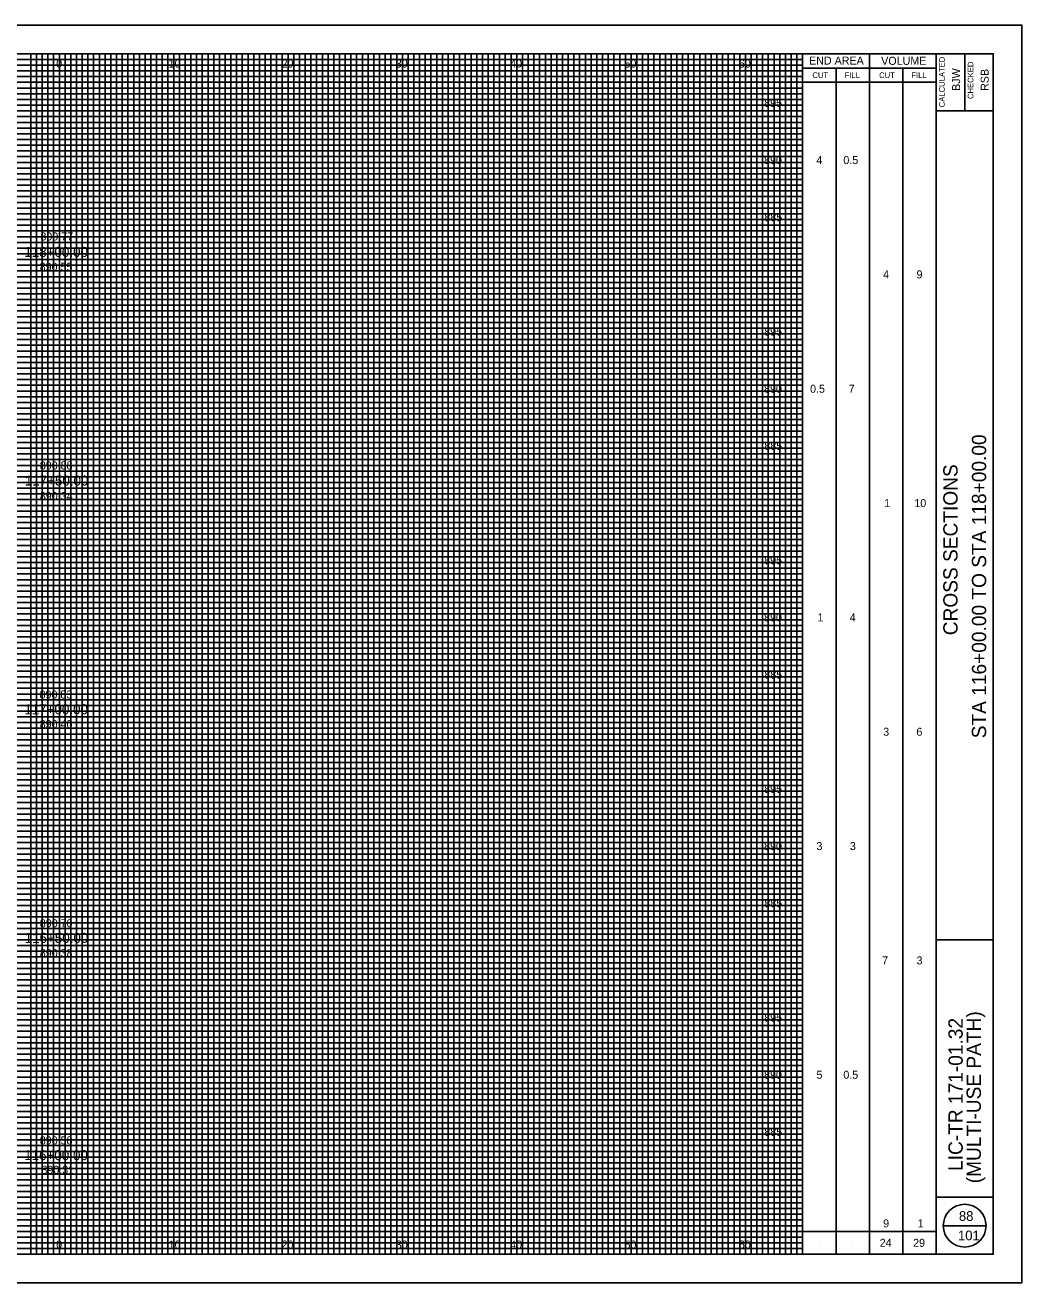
# Model space of a CAD drawing. Extents: x -10 to 160, y -2 to 3672.
# Drawn here: x 72.8 to 160, y 2182.5 to 2292.5 of the extents above; entities that cross this region are included whole.
import ezdxf

# ---------------------------------------------------------------- set-up
doc = ezdxf.new("R2010")
doc.units = 0
for name, color, linetype in [('SH_Border', 7, 'Continuous'), ('SH_Cut_Line', 7, 'Continuous'), ('SH_Data', 7, 'Continuous'), ('SH_Major_Grid_Line', 7, 'Continuous'), ('SH_Minor_Grid_Line', 7, 'Continuous'), ('SH_Text', 7, 'Continuous'), ('TX_P_10', 7, 'Continuous'), ('TX_X_10', 7, 'Continuous')]:
    doc.layers.add(name, color=color, linetype=linetype)

msp = doc.modelspace()

# ---------------------------------------------------------------- linework, layer by layer
at = {"layer": 'SH_Border'}
for p, q in [((152.5, 2185), (152.5, 2290)), ((155, 2290), (155, 2285)), ((152.5, 2285), (157.5, 2285)), ((152.5, 2212.5), (157.5, 2212.5)), ((152.5, 2190), (157.5, 2190))]:
    msp.add_line(p, q, dxfattribs=at)
msp.add_lwpolyline([(0, 2290), (157.5, 2290), (157.5, 2185), (0, 2185)], close=True, dxfattribs=at)
at = {"layer": 'SH_Cut_Line'}
msp.add_lwpolyline([(-10, 2182.5), (160, 2182.5), (160, 2292.5), (-10, 2292.5)], close=True, dxfattribs=at)
at = {"layer": 'SH_Data'}
for p, q in [((140.83, 2185), (140.83, 2290)), ((146.67, 2185), (146.67, 2290)), ((140.83, 2288.75), (152.5, 2288.75)), ((143.75, 2185), (143.75, 2288.75)), ((149.58, 2185), (149.58, 2288.75)), ((140.83, 2287.5), (152.5, 2287.5)), ((140.83, 2187), (152.5, 2187)), ((153.12, 2187.5), (156.88, 2187.5)), ((142.29, 2186), (142.29, 2186)), ((145.21, 2186), (145.21, 2186)), ((148.12, 2186), (148.12, 2186)), ((151.04, 2186), (151.04, 2186))]:
    msp.add_line(p, q, dxfattribs=at)
msp.add_circle((155, 2187.5), 1.87, dxfattribs=at)
at = {"layer": 'SH_Major_Grid_Line'}
for p, q in [((75.83, 2185), (75.83, 2290)), ((80.83, 2185), (80.83, 2290)), ((85.83, 2185), (85.83, 2290)), ((90.83, 2185), (90.83, 2290)), ((95.83, 2185), (95.83, 2290)), ((100.83, 2185), (100.83, 2290)), ((105.83, 2185), (105.83, 2290)), ((110.83, 2185), (110.83, 2290)), ((115.83, 2185), (115.83, 2290)), ((120.83, 2185), (120.83, 2290)), ((125.83, 2185), (125.83, 2290)), ((130.83, 2185), (130.83, 2290)), ((135.83, 2185), (135.83, 2290)), ((5.83, 2285), (140.83, 2285)), ((5.83, 2280), (140.83, 2280)), ((5.83, 2275), (140.83, 2275)), ((5.83, 2270), (140.83, 2270)), ((5.83, 2265), (140.83, 2265)), ((5.83, 2260), (140.83, 2260)), ((5.83, 2255), (140.83, 2255)), ((5.83, 2250), (140.83, 2250)), ((5.83, 2245), (140.83, 2245)), ((5.83, 2240), (140.83, 2240)), ((5.83, 2235), (140.83, 2235)), ((5.83, 2230), (140.83, 2230)), ((5.83, 2225), (140.83, 2225)), ((5.83, 2220), (140.83, 2220)), ((5.83, 2215), (140.83, 2215)), ((5.83, 2210), (140.83, 2210)), ((5.83, 2205), (140.83, 2205)), ((5.83, 2200), (140.83, 2200)), ((5.83, 2195), (140.83, 2195)), ((5.83, 2190), (140.83, 2190))]:
    msp.add_line(p, q, dxfattribs=at)
at = {"layer": 'SH_Minor_Grid_Line'}
for p, q in [((5.83, 2289.5), (140.83, 2289.5)), ((73.33, 2185), (73.33, 2290)), ((73.83, 2185), (73.83, 2290)), ((74.33, 2185), (74.33, 2290)), ((74.83, 2185), (74.83, 2290)), ((75.33, 2185), (75.33, 2290)), ((76.33, 2185), (76.33, 2290)), ((76.83, 2185), (76.83, 2290)), ((77.33, 2185), (77.33, 2290)), ((77.83, 2185), (77.83, 2290)), ((78.33, 2185), (78.33, 2290)), ((78.83, 2185), (78.83, 2290)), ((79.33, 2185), (79.33, 2290)), ((79.83, 2185), (79.83, 2290)), ((80.33, 2185), (80.33, 2290)), ((81.33, 2185), (81.33, 2290)), ((81.83, 2185), (81.83, 2290)), ((82.33, 2185), (82.33, 2290)), ((82.83, 2185), (82.83, 2290)), ((83.33, 2185), (83.33, 2290)), ((83.83, 2185), (83.83, 2290)), ((84.33, 2185), (84.33, 2290)), ((84.83, 2185), (84.83, 2290)), ((85.33, 2185), (85.33, 2290)), ((86.33, 2185), (86.33, 2290)), ((86.83, 2185), (86.83, 2290)), ((87.33, 2185), (87.33, 2290)), ((87.83, 2185), (87.83, 2290)), ((88.33, 2185), (88.33, 2290)), ((88.83, 2185), (88.83, 2290)), ((89.33, 2185), (89.33, 2290)), ((89.83, 2185), (89.83, 2290)), ((90.33, 2185), (90.33, 2290)), ((91.33, 2185), (91.33, 2290)), ((91.83, 2185), (91.83, 2290)), ((92.33, 2185), (92.33, 2290)), ((92.83, 2185), (92.83, 2290)), ((93.33, 2185), (93.33, 2290)), ((93.83, 2185), (93.83, 2290)), ((94.33, 2185), (94.33, 2290)), ((94.83, 2185), (94.83, 2290)), ((95.33, 2185), (95.33, 2290)), ((96.33, 2185), (96.33, 2290)), ((96.83, 2185), (96.83, 2290)), ((97.33, 2185), (97.33, 2290)), ((97.83, 2185), (97.83, 2290)), ((98.33, 2185), (98.33, 2290)), ((98.83, 2185), (98.83, 2290)), ((99.33, 2185), (99.33, 2290)), ((99.83, 2185), (99.83, 2290)), ((100.33, 2185), (100.33, 2290)), ((101.33, 2185), (101.33, 2290)), ((101.83, 2185), (101.83, 2290)), ((102.33, 2185), (102.33, 2290)), ((102.83, 2185), (102.83, 2290)), ((103.33, 2185), (103.33, 2290)), ((103.83, 2185), (103.83, 2290)), ((104.33, 2185), (104.33, 2290)), ((104.83, 2185), (104.83, 2290)), ((105.33, 2185), (105.33, 2290)), ((106.33, 2185), (106.33, 2290)), ((106.83, 2185), (106.83, 2290)), ((107.33, 2185), (107.33, 2290)), ((107.83, 2185), (107.83, 2290)), ((108.33, 2185), (108.33, 2290)), ((108.83, 2185), (108.83, 2290)), ((109.33, 2185), (109.33, 2290)), ((109.83, 2185), (109.83, 2290)), ((110.33, 2185), (110.33, 2290)), ((111.33, 2185), (111.33, 2290)), ((111.83, 2185), (111.83, 2290)), ((112.33, 2185), (112.33, 2290)), ((112.83, 2185), (112.83, 2290)), ((113.33, 2185), (113.33, 2290)), ((113.83, 2185), (113.83, 2290)), ((114.33, 2185), (114.33, 2290)), ((114.83, 2185), (114.83, 2290)), ((115.33, 2185), (115.33, 2290)), ((116.33, 2185), (116.33, 2290)), ((116.83, 2185), (116.83, 2290)), ((117.33, 2185), (117.33, 2290)), ((117.83, 2185), (117.83, 2290)), ((118.33, 2185), (118.33, 2290)), ((118.83, 2185), (118.83, 2290)), ((119.33, 2185), (119.33, 2290)), ((119.83, 2185), (119.83, 2290)), ((120.33, 2185), (120.33, 2290)), ((121.33, 2185), (121.33, 2290)), ((121.83, 2185), (121.83, 2290)), ((122.33, 2185), (122.33, 2290)), ((122.83, 2185), (122.83, 2290)), ((123.33, 2185), (123.33, 2290)), ((123.83, 2185), (123.83, 2290)), ((124.33, 2185), (124.33, 2290)), ((124.83, 2185), (124.83, 2290)), ((125.33, 2185), (125.33, 2290)), ((126.33, 2185), (126.33, 2290)), ((126.83, 2185), (126.83, 2290)), ((127.33, 2185), (127.33, 2290)), ((127.83, 2185), (127.83, 2290)), ((128.33, 2185), (128.33, 2290)), ((128.83, 2185), (128.83, 2290)), ((129.33, 2185), (129.33, 2290)), ((129.83, 2185), (129.83, 2290)), ((130.33, 2185), (130.33, 2290)), ((131.33, 2185), (131.33, 2290)), ((131.83, 2185), (131.83, 2290)), ((132.33, 2185), (132.33, 2290)), ((132.83, 2185), (132.83, 2290)), ((133.33, 2185), (133.33, 2290)), ((133.83, 2185), (133.83, 2290)), ((134.33, 2185), (134.33, 2290)), ((134.83, 2185), (134.83, 2290)), ((135.33, 2185), (135.33, 2290)), ((136.33, 2185), (136.33, 2290)), ((136.83, 2185), (136.83, 2290)), ((137.33, 2185), (137.33, 2290)), ((137.83, 2185), (137.83, 2290)), ((138.33, 2185), (138.33, 2290)), ((138.83, 2185), (138.83, 2290)), ((139.33, 2185), (139.33, 2290)), ((139.83, 2185), (139.83, 2290)), ((140.33, 2185), (140.33, 2290)), ((5.83, 2289), (140.83, 2289)), ((5.83, 2288.5), (140.83, 2288.5)), ((5.83, 2288), (140.83, 2288)), ((5.83, 2287.5), (140.83, 2287.5)), ((5.83, 2287), (140.83, 2287)), ((5.83, 2286.5), (140.83, 2286.5)), ((5.83, 2286), (140.83, 2286)), ((5.83, 2285.5), (140.83, 2285.5)), ((5.83, 2284.5), (140.83, 2284.5)), ((5.83, 2284), (140.83, 2284)), ((5.83, 2283.5), (140.83, 2283.5)), ((5.83, 2283), (140.83, 2283)), ((5.83, 2282.5), (140.83, 2282.5)), ((5.83, 2282), (140.83, 2282)), ((5.83, 2281.5), (140.83, 2281.5)), ((5.83, 2281), (140.83, 2281)), ((5.83, 2280.5), (140.83, 2280.5)), ((5.83, 2279.5), (140.83, 2279.5)), ((5.83, 2279), (140.83, 2279)), ((5.83, 2278.5), (140.83, 2278.5)), ((5.83, 2278), (140.83, 2278)), ((5.83, 2277.5), (140.83, 2277.5)), ((5.83, 2277), (140.83, 2277)), ((5.83, 2276.5), (140.83, 2276.5)), ((5.83, 2276), (140.83, 2276)), ((5.83, 2275.5), (140.83, 2275.5)), ((5.83, 2274.5), (140.83, 2274.5)), ((5.83, 2274), (140.83, 2274)), ((5.83, 2273.5), (140.83, 2273.5)), ((5.83, 2273), (140.83, 2273)), ((5.83, 2272.5), (140.83, 2272.5)), ((5.83, 2272), (140.83, 2272)), ((5.83, 2271.5), (140.83, 2271.5)), ((5.83, 2271), (140.83, 2271)), ((5.83, 2270.5), (140.83, 2270.5)), ((5.83, 2269.5), (140.83, 2269.5)), ((5.83, 2269), (140.83, 2269)), ((5.83, 2268.5), (140.83, 2268.5)), ((5.83, 2268), (140.83, 2268)), ((5.83, 2267.5), (140.83, 2267.5)), ((5.83, 2267), (140.83, 2267)), ((5.83, 2266.5), (140.83, 2266.5)), ((5.83, 2266), (140.83, 2266)), ((5.83, 2265.5), (140.83, 2265.5)), ((5.83, 2264.5), (140.83, 2264.5)), ((5.83, 2264), (140.83, 2264)), ((5.83, 2263.5), (140.83, 2263.5)), ((5.83, 2263), (140.83, 2263)), ((5.83, 2262.5), (140.83, 2262.5)), ((5.83, 2262), (140.83, 2262)), ((5.83, 2261.5), (140.83, 2261.5)), ((5.83, 2261), (140.83, 2261)), ((5.83, 2260.5), (140.83, 2260.5)), ((5.83, 2259.5), (140.83, 2259.5)), ((5.83, 2259), (140.83, 2259)), ((5.83, 2258.5), (140.83, 2258.5)), ((5.83, 2258), (140.83, 2258)), ((5.83, 2257.5), (140.83, 2257.5)), ((5.83, 2257), (140.83, 2257)), ((5.83, 2256.5), (140.83, 2256.5)), ((5.83, 2256), (140.83, 2256)), ((5.83, 2255.5), (140.83, 2255.5)), ((5.83, 2254.5), (140.83, 2254.5)), ((5.83, 2254), (140.83, 2254)), ((5.83, 2253.5), (140.83, 2253.5)), ((5.83, 2253), (140.83, 2253)), ((5.83, 2252.5), (140.83, 2252.5)), ((5.83, 2252), (140.83, 2252)), ((5.83, 2251.5), (140.83, 2251.5)), ((5.83, 2251), (140.83, 2251)), ((5.83, 2250.5), (140.83, 2250.5)), ((5.83, 2249.5), (140.83, 2249.5)), ((5.83, 2249), (140.83, 2249)), ((5.83, 2248.5), (140.83, 2248.5)), ((5.83, 2248), (140.83, 2248)), ((5.83, 2247.5), (140.83, 2247.5)), ((5.83, 2247), (140.83, 2247)), ((5.83, 2246.5), (140.83, 2246.5)), ((5.83, 2246), (140.83, 2246)), ((5.83, 2245.5), (140.83, 2245.5)), ((5.83, 2244.5), (140.83, 2244.5)), ((5.83, 2244), (140.83, 2244)), ((5.83, 2243.5), (140.83, 2243.5)), ((5.83, 2243), (140.83, 2243)), ((5.83, 2242.5), (140.83, 2242.5)), ((5.83, 2242), (140.83, 2242)), ((5.83, 2241.5), (140.83, 2241.5)), ((5.83, 2241), (140.83, 2241)), ((5.83, 2240.5), (140.83, 2240.5)), ((5.83, 2239.5), (140.83, 2239.5)), ((5.83, 2239), (140.83, 2239)), ((5.83, 2238.5), (140.83, 2238.5)), ((5.83, 2238), (140.83, 2238)), ((5.83, 2237.5), (140.83, 2237.5)), ((5.83, 2237), (140.83, 2237)), ((5.83, 2236.5), (140.83, 2236.5)), ((5.83, 2236), (140.83, 2236)), ((5.83, 2235.5), (140.83, 2235.5)), ((5.83, 2234.5), (140.83, 2234.5)), ((5.83, 2234), (140.83, 2234)), ((5.83, 2233.5), (140.83, 2233.5)), ((5.83, 2233), (140.83, 2233)), ((5.83, 2232.5), (140.83, 2232.5)), ((5.83, 2232), (140.83, 2232)), ((5.83, 2231.5), (140.83, 2231.5)), ((5.83, 2231), (140.83, 2231)), ((5.83, 2230.5), (140.83, 2230.5)), ((5.83, 2229.5), (140.83, 2229.5)), ((5.83, 2229), (140.83, 2229)), ((5.83, 2228.5), (140.83, 2228.5)), ((5.83, 2228), (140.83, 2228)), ((5.83, 2227.5), (140.83, 2227.5)), ((5.83, 2227), (140.83, 2227)), ((5.83, 2226.5), (140.83, 2226.5)), ((5.83, 2226), (140.83, 2226)), ((5.83, 2225.5), (140.83, 2225.5)), ((5.83, 2224.5), (140.83, 2224.5)), ((5.83, 2224), (140.83, 2224)), ((5.83, 2223.5), (140.83, 2223.5)), ((5.83, 2223), (140.83, 2223)), ((5.83, 2222.5), (140.83, 2222.5)), ((5.83, 2222), (140.83, 2222)), ((5.83, 2221.5), (140.83, 2221.5)), ((5.83, 2221), (140.83, 2221)), ((5.83, 2220.5), (140.83, 2220.5)), ((5.83, 2219.5), (140.83, 2219.5)), ((5.83, 2219), (140.83, 2219)), ((5.83, 2218.5), (140.83, 2218.5)), ((5.83, 2218), (140.83, 2218)), ((5.83, 2217.5), (140.83, 2217.5)), ((5.83, 2217), (140.83, 2217)), ((5.83, 2216.5), (140.83, 2216.5)), ((5.83, 2216), (140.83, 2216)), ((5.83, 2215.5), (140.83, 2215.5)), ((5.83, 2214.5), (140.83, 2214.5)), ((5.83, 2214), (140.83, 2214)), ((5.83, 2213.5), (140.83, 2213.5)), ((5.83, 2213), (140.83, 2213)), ((5.83, 2212.5), (140.83, 2212.5)), ((5.83, 2212), (140.83, 2212)), ((5.83, 2211.5), (140.83, 2211.5)), ((5.83, 2211), (140.83, 2211)), ((5.83, 2210.5), (140.83, 2210.5)), ((5.83, 2209.5), (140.83, 2209.5)), ((5.83, 2209), (140.83, 2209)), ((5.83, 2208.5), (140.83, 2208.5)), ((5.83, 2208), (140.83, 2208)), ((5.83, 2207.5), (140.83, 2207.5)), ((5.83, 2207), (140.83, 2207)), ((5.83, 2206.5), (140.83, 2206.5)), ((5.83, 2206), (140.83, 2206)), ((5.83, 2205.5), (140.83, 2205.5)), ((5.83, 2204.5), (140.83, 2204.5)), ((5.83, 2204), (140.83, 2204)), ((5.83, 2203.5), (140.83, 2203.5)), ((5.83, 2203), (140.83, 2203)), ((5.83, 2202.5), (140.83, 2202.5)), ((5.83, 2202), (140.83, 2202)), ((5.83, 2201.5), (140.83, 2201.5)), ((5.83, 2201), (140.83, 2201)), ((5.83, 2200.5), (140.83, 2200.5)), ((5.83, 2199.5), (140.83, 2199.5)), ((5.83, 2199), (140.83, 2199)), ((5.83, 2198.5), (140.83, 2198.5)), ((5.83, 2198), (140.83, 2198)), ((5.83, 2197.5), (140.83, 2197.5)), ((5.83, 2197), (140.83, 2197)), ((5.83, 2196.5), (140.83, 2196.5)), ((5.83, 2196), (140.83, 2196)), ((5.83, 2195.5), (140.83, 2195.5)), ((5.83, 2194.5), (140.83, 2194.5)), ((5.83, 2194), (140.83, 2194)), ((5.83, 2193.5), (140.83, 2193.5)), ((5.83, 2193), (140.83, 2193)), ((5.83, 2192.5), (140.83, 2192.5)), ((5.83, 2192), (140.83, 2192)), ((5.83, 2191.5), (140.83, 2191.5)), ((5.83, 2191), (140.83, 2191)), ((5.83, 2190.5), (140.83, 2190.5)), ((5.83, 2189.5), (140.83, 2189.5)), ((5.83, 2189), (140.83, 2189)), ((5.83, 2188.5), (140.83, 2188.5)), ((5.83, 2188), (140.83, 2188)), ((5.83, 2187.5), (140.83, 2187.5)), ((5.83, 2187), (140.83, 2187)), ((5.83, 2186.5), (140.83, 2186.5)), ((5.83, 2186), (140.83, 2186)), ((5.83, 2185.5), (140.83, 2185.5))]:
    msp.add_line(p, q, dxfattribs=at)

# ---------------------------------------------------------------- texts
at = {"layer": 'SH_Data'}
for s, height, p in [('END AREA', 0.7, (141.39, 2289.05)), ('VOLUME', 0.7, (147.7, 2289.03)), ('CUT', 0.5, (141.68, 2287.87)), ('FILL', 0.5, (144.5, 2287.87)), ('CUT', 0.5, (147.52, 2287.87)), ('FILL', 0.5, (150.34, 2287.87)), ('88', 0.85, (154.5, 2187.92)), ('101', 0.85, (154.42, 2186.22))]:
    msp.add_text(s, height=height, dxfattribs=at).set_placement(p)
for s, height, p in [('CALCULATED', 0.5, (153.26, 2285.32)), ('CHECKED', 0.5, (155.76, 2286.04)), ('BJW', 0.7, (154.6, 2286.75)), ('RSB', 0.7, (157.1, 2286.75)), ('STA 116+00.00 TO STA 118+00.00', 1.25, (156.88, 2230.13)), ('CROSS SECTIONS', 1.25, (154.38, 2239.14)), ('LIC-TR 171-01.32', 1.25, (154.83, 2192.29)), ('(MULTI-USE PATH)', 1.25, (156.42, 2191.21))]:
    msp.add_text(s, height=height, rotation=90, dxfattribs=at).set_placement(p)
at = {"layer": 'SH_Text'}
for s, height, p in [('0', 0.7, (75.55, 2288.79)), ('10', 0.7, (85.39, 2288.79)), ('20', 0.7, (95.26, 2288.79)), ('30', 0.7, (105.25, 2288.79)), ('40', 0.7, (115.25, 2288.79)), ('50', 0.7, (125.25, 2288.79)), ('60', 0.7, (135.25, 2288.79)), ('895', 0.7, (137.47, 2285.35)), ('890', 0.7, (137.46, 2280.35)), ('4', 0.7, (142.03, 2280.35)), ('0.5', 0.7, (144.39, 2280.35)), ('885', 0.7, (137.48, 2275.35)), ('118+00.00', 0.875, (72.77, 2272.23)), ('4', 0.7, (147.87, 2270.35)), ('9', 0.7, (150.79, 2270.35)), ('895', 0.7, (137.47, 2265.35)), ('890', 0.7, (137.46, 2260.35)), ('0.5', 0.7, (141.48, 2260.35)), ('7', 0.7, (144.86, 2260.35)), ('885', 0.7, (137.48, 2255.35)), ('117+50.00', 0.875, (72.81, 2252.23)), ('1', 0.7, (147.96, 2250.35)), ('10', 0.7, (150.6, 2250.35)), ('895', 0.7, (137.47, 2245.35)), ('890', 0.7, (137.46, 2240.35)), ('1', 0.7, (142.13, 2240.35)), ('4', 0.7, (144.95, 2240.35)), ('885', 0.7, (137.48, 2235.35)), ('117+00.00', 0.875, (72.77, 2232.23)), ('3', 0.7, (147.88, 2230.35)), ('6', 0.7, (150.78, 2230.35)), ('895', 0.7, (137.47, 2225.35)), ('890', 0.7, (137.46, 2220.35)), ('3', 0.7, (142.04, 2220.35)), ('3', 0.7, (144.96, 2220.35)), ('885', 0.7, (137.48, 2215.35)), ('116+50.00', 0.875, (72.8, 2212.23)), ('7', 0.7, (147.78, 2210.35)), ('3', 0.7, (150.79, 2210.35)), ('895', 0.7, (137.47, 2205.35)), ('890', 0.7, (137.46, 2200.35)), ('5', 0.7, (142.04, 2200.35)), ('0.5', 0.7, (144.39, 2200.35)), ('885', 0.7, (137.48, 2195.35)), ('116+00.00', 0.875, (72.76, 2193.23)), ('9', 0.7, (147.87, 2187.35)), ('1', 0.7, (150.88, 2187.35)), ('0', 0.7, (75.55, 2185.5)), ('10', 0.7, (85.39, 2185.5)), ('20', 0.7, (95.26, 2185.5)), ('30', 0.7, (105.25, 2185.5)), ('40', 0.7, (115.25, 2185.5)), ('50', 0.7, (125.25, 2185.5)), ('60', 0.7, (135.25, 2185.5)), ('24', 0.7, (147.57, 2185.65)), ('29', 0.7, (150.49, 2185.65))]:
    msp.add_text(s, height=height, dxfattribs=at).set_placement(p)
at = {"layer": 'TX_P_10'}
for s, p in [('890.77', (74.17, 2273.67)), ('890.88', (74.12, 2253.64)), ('890.83', (74.1, 2233.61)), ('890.70', (74.12, 2213.6)), ('890.58', (74.12, 2194.61))]:
    msp.add_text(s, height=0.7, dxfattribs=at).set_placement(p)
at = {"layer": 'TX_X_10'}
for s, p in [('890.55', (74.11, 2271.02)), ('890.34', (74.12, 2250.96)), ('890.40', (74.11, 2231.02)), ('890.38', (74.12, 2211)), ('890.31', (74.26, 2192.04))]:
    msp.add_text(s, height=0.7, dxfattribs=at).set_placement(p)

doc.saveas('drawing.dxf')
